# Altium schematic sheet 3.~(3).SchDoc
size 420 x 297 mm
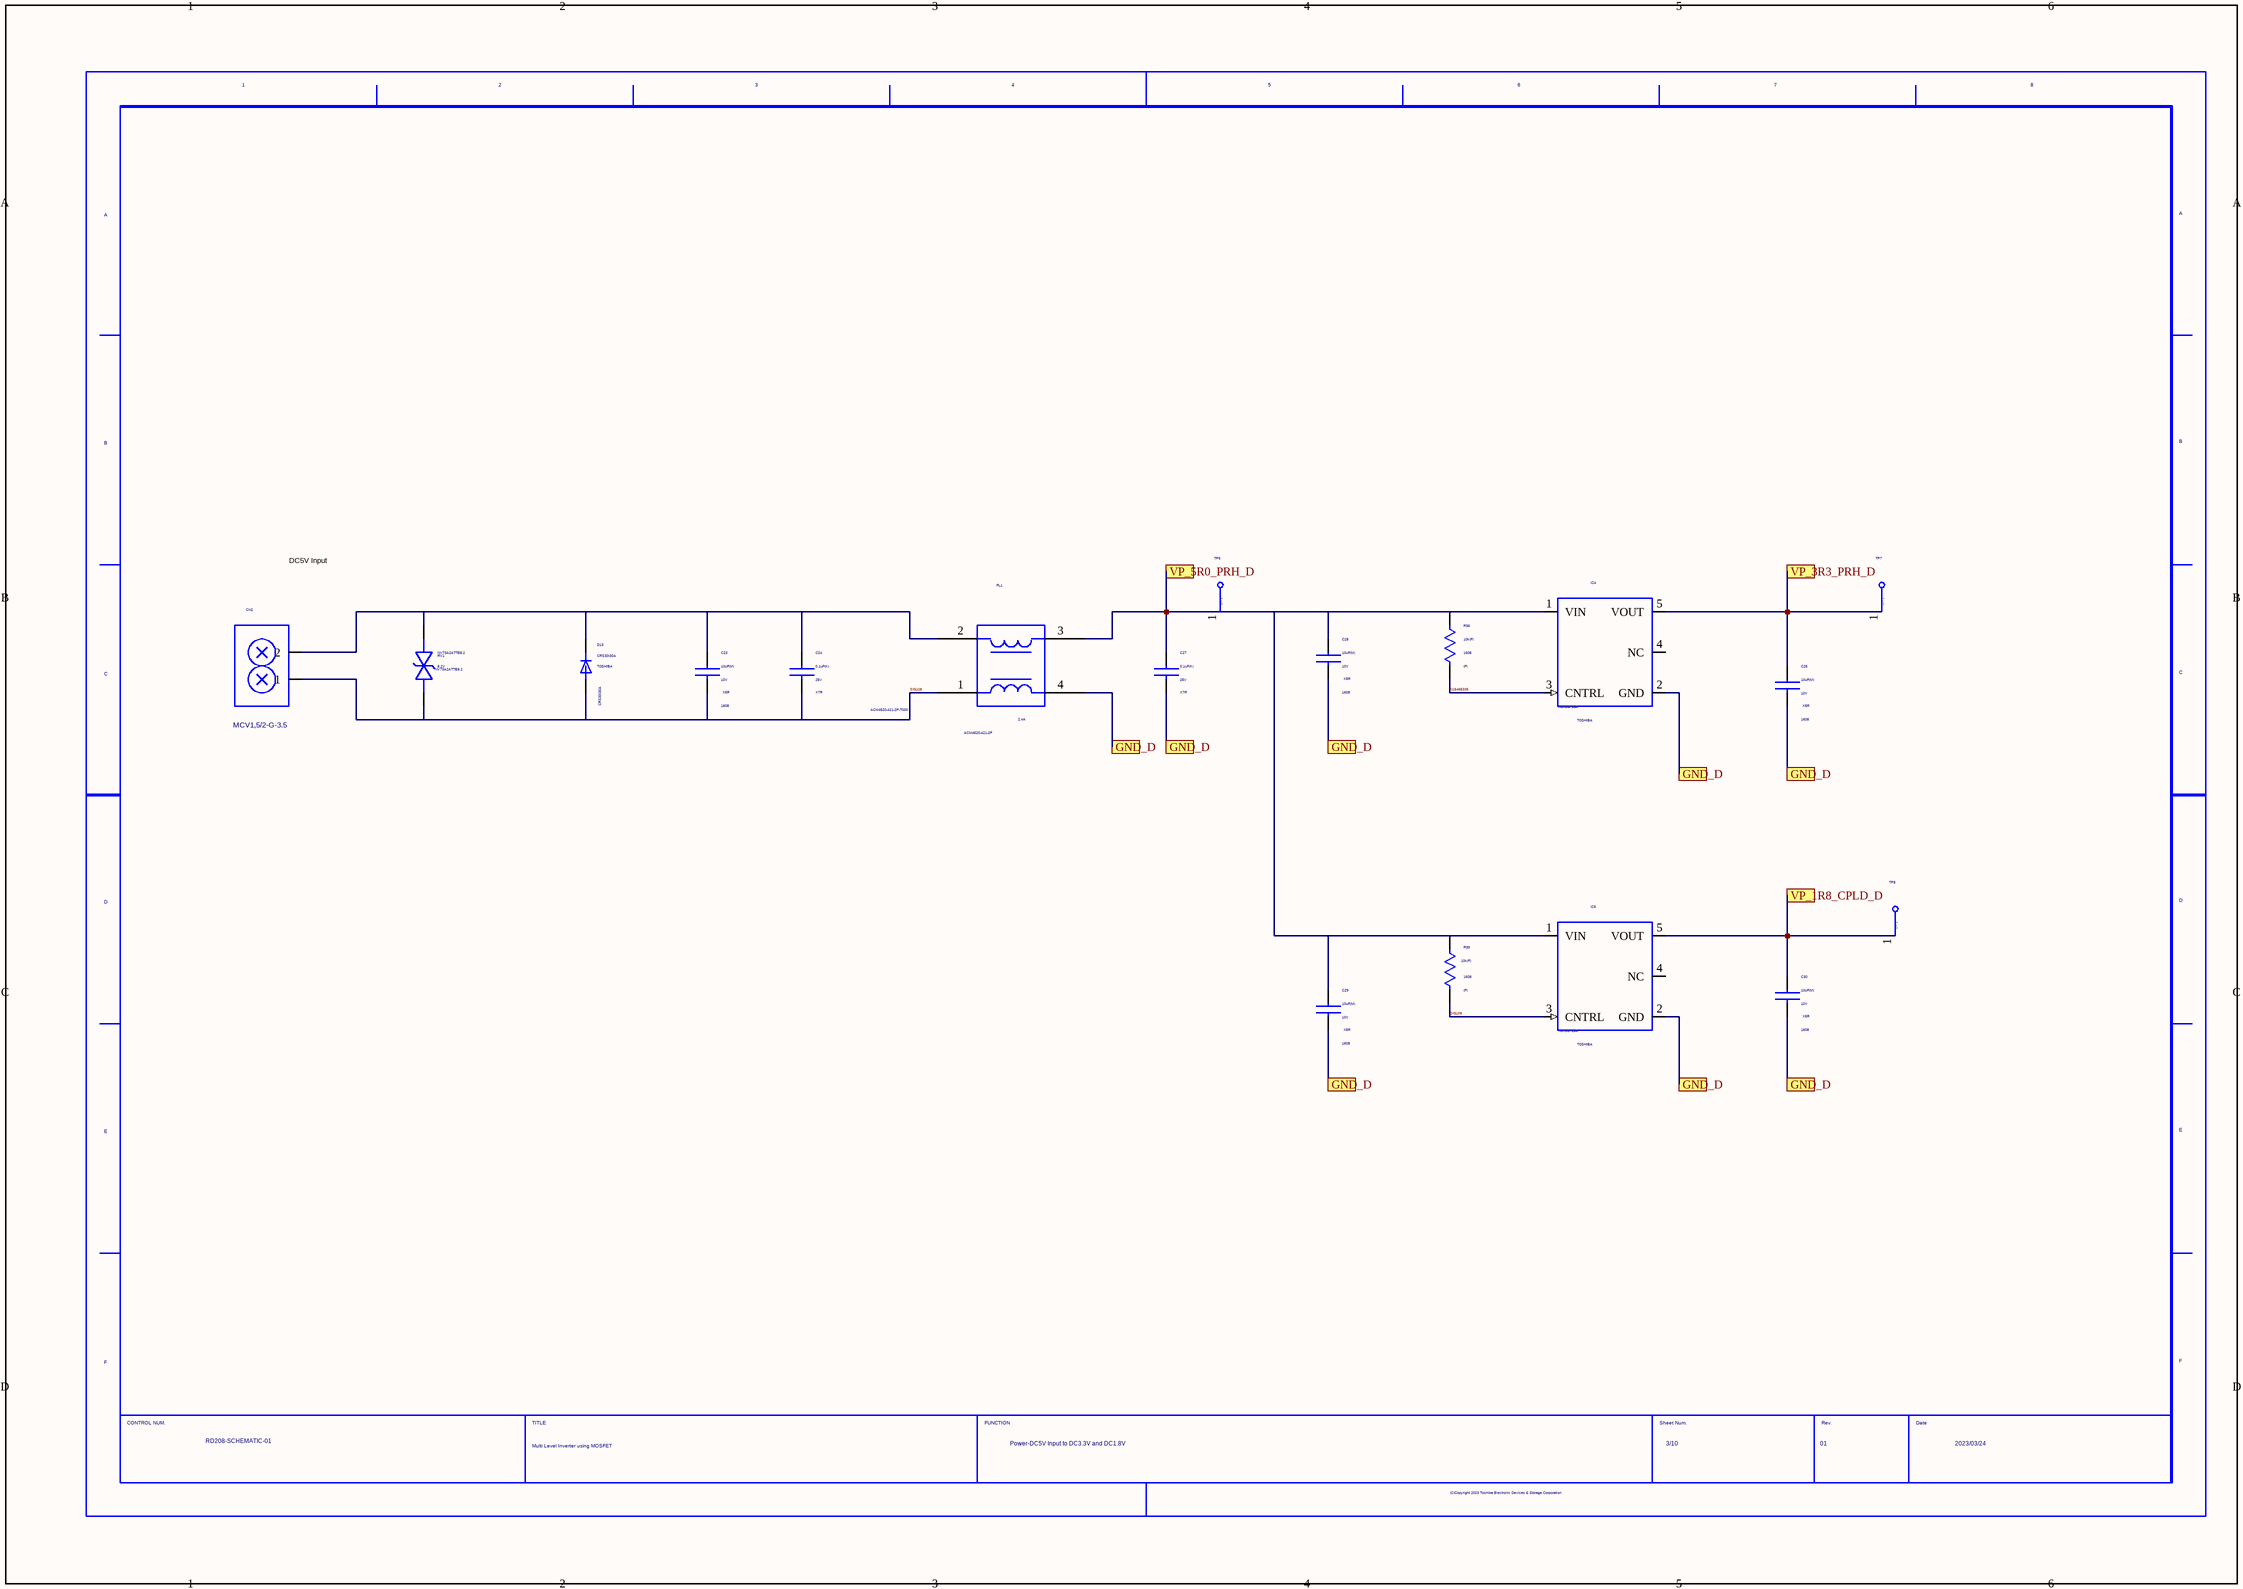
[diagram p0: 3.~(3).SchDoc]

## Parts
C23  VAL2: 10V  SIZECODESMD: 1608  VALUE4: X5R  VAL1: 10uF(M)  (hidden comment: GRM188R61A106ME69D)
C24  VAL2: 25V  VALUE4: X7R  VAL1: 0.1uF(K)  (hidden comment: GRM155R71E104KE14D)
C25  VAL2: 10V  SIZECODESMD: 1608  VALUE4: X5R  VAL1: 10uF(M)  (hidden comment: GRM188R61A106ME69D)
C27  VAL2: 25V  VALUE4: X7R  VAL1: 0.1uF(K)  (hidden comment: GRM155R71E104KE14D)
C28  VAL2: 10V  SIZECODESMD: 1608  VALUE4: X5R  VAL1: 10uF(M)  (hidden comment: GRM188R61A106ME69D)
C29  VAL2: 10V  SIZECODESMD: 1608  VALUE4: X5R  VAL1: 10uF(M)  (hidden comment: GRM188R61A106ME69D)
C30  VAL2: 10V  SIZECODESMD: 1608  VALUE4: X5R  VAL1: 10uF(M)  (hidden comment: GRM188R61A106ME69D)
CN2  SCH_NAME: MCV1,5/2-G-3.5  (hidden comment: 1843606)
D13  USERCOMPTEXT3: TOSHIBA  (hidden comment: CRS30I30A)
FL1  VAL2: 2.4A  VAL1: ACM4520-421-2P-T000  SCH_NAME: ACM4520-421-2P  (hidden comment: ACM4520_421_2P_T000)
IC4  USERCOMPTEXT3: TOSHIBA  (hidden comment: TCR3UF33A)
IC5  USERCOMPTEXT3: TOSHIBA  VAL3: TCR3UF18A  (hidden comment: TCR3UF33A)
R36  SIZECODESMD: 1608  VALUE4: (F)  VAL1: 10k(F)  (hidden comment: ERJ3EKF1002V)
R39  SIZECODESMD: 1608  VALUE4: (F)  VAL1: 10k(F)  (hidden comment: ERJ3EKF1002V)
RV1  VAL2: 8.2V  VAL1: NV73A2ATTE8.2  (hidden comment: NV73A2ATTE8_2)
TP6  TP  (value not drawn)
TP7  TP  (value not drawn)
TP8  TP  (value not drawn)
U?  DATE: 2023/03/24  TITLE: Multi Level Inverter using MOSFET  DRAWINGNUMBER: RD208-SCHEMATIC-01  REVISION: 01  SHEETNUMBER: 3/10  FUNCTION: Power-DC5V Input to DC3.3V and DC1.8V  (hidden comment: WAKU_DEF100)

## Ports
GND_D, VP_1R8_CPLD_D, VP_3R3_PRH_D, VP_5R0_PRH_D

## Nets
5V_IN: C23.1 C24.1 CN2.2 D13.K(CATHODE) FL1.2(CB) RV1.2(C)
GND_D: C25.2 C27.2 C28.2 C29.2 C30.2 FL1.4(CG4) IC4.2(GND) IC5.2(GND) ; port GND_D
N16465335: IC4.3(CNTRL) R36.2
SIG108: C23.2 C24.2 CN2.1 D13.A(ANODE) FL1.1(B) RV1.1(A)
SIG109: IC5.3(CNTRL) R39.2
VP_1R8_CPLD_D: C30.1 IC5.5(VOUT) TP8.1 ; port VP_1R8_CPLD_D
VP_3R3_PRH_D: C25.1 IC4.5(VOUT) TP7.1 ; port VP_3R3_PRH_D
VP_5R0_PRH_D: C27.1 C28.1 C29.1 FL1.3(PSG) IC4.1(VIN) IC5.1(VIN) R36.1 R39.1 TP6.1 ; port VP_5R0_PRH_D

Not connected (* = marked no-connect by the designer): IC4 4(NC); IC5 4(NC)

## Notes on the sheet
- DC5V Input

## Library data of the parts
C23 = GRM188R61A106ME69D: MANUFACTURER: MURATA; ITEM: CAP Ceramic; TIME: 08:44:46; UPDATEUSER: t5459927; SAVECOUNT: 1; OriginalSymbolOrigin: (0,0); INSTANCENAME: INS16466301
C24 = GRM155R71E104KE14D: MANUFACTURER: MURATA; ITEM: CAP Ceramic; SIZECODESMD: 1005; TIME: 08:44:45; UPDATEUSER: t5459927; SAVECOUNT: 1; OriginalSymbolOrigin: (0,0); INSTANCENAME: INS16466561
C25 = GRM188R61A106ME69D: MANUFACTURER: MURATA; ITEM: CAP Ceramic; TIME: 08:44:46; UPDATEUSER: t5459927; SAVECOUNT: 1; OriginalSymbolOrigin: (0,0); INSTANCENAME: INS16465857
C27 = GRM155R71E104KE14D: MANUFACTURER: MURATA; ITEM: CAP Ceramic; SIZECODESMD: 1005; TIME: 08:44:45; UPDATEUSER: t5459927; SAVECOUNT: 1; OriginalSymbolOrigin: (0,0); INSTANCENAME: INS16466055
C28 = GRM188R61A106ME69D: MANUFACTURER: MURATA; ITEM: CAP Ceramic; TIME: 08:44:46; UPDATEUSER: t5459927; SAVECOUNT: 1; OriginalSymbolOrigin: (0,0); INSTANCENAME: INS16466267
C29 = GRM188R61A106ME69D: MANUFACTURER: MURATA; ITEM: CAP Ceramic; TIME: 08:44:46; UPDATEUSER: t5459927; SAVECOUNT: 1; OriginalSymbolOrigin: (0,0); INSTANCENAME: INS16465891
C30 = GRM188R61A106ME69D: MANUFACTURER: MURATA; ITEM: CAP Ceramic; TIME: 08:44:46; UPDATEUSER: t5459927; SAVECOUNT: 1; OriginalSymbolOrigin: (0,0); INSTANCENAME: INS16466167
CN2 = 1843606: MANUFACTURER: PHOENIX CONTACT; ITEM: Connector 2Pin Terminal Block; TIME: 08:44:48; UPDATEUSER: t5459927; SAVECOUNT: 1; SAVEAREA0: -7641,-15544,14757,852; OriginalSymbolOrigin: (0,0); INSTANCENAME: INS16809162
D13 = CRS30I30A: ITEM: DIODE; TIME: 08:44:48; UPDATEUSER: t5459927; SAVECOUNT: 1; OriginalSymbolOrigin: (0,0); INSTANCENAME: INS17152863
FL1 = ACM4520_421_2P_T000: MANUFACTURER: TDK; ITEM: Filter; TIME: 08:44:48; UPDATEUSER: t5459927; SAVECOUNT: 1; SAVEAREA0: -11402,-15649,23384,1144; OriginalSymbolOrigin: (0,0); INSTANCENAME: INS16465959
IC4 IC5 = TCR3UF33A: ITEM: IC LDO; VAL2: LDO; TIME: 08:44:48; UPDATEUSER: PS4_common_PC; UPDATETIME: 15:57:17; SAVECOUNT: 3; SAVEAREA0: -27364,-26218,44601,6573; OriginalSymbolOrigin: (0,0)
R36 = ERJ3EKF1002V: MANUFACTURER: Panasonic; ITEM: Register; VAL2: 100mW; TIME: 08:44:46; UPDATEUSER: t5459927; SAVECOUNT: 1; OriginalSymbolOrigin: (0,0); INSTANCENAME: INS16466335
R39 = ERJ3EKF1002V: MANUFACTURER: Panasonic; ITEM: Register; VAL2: 100mW; TIME: 08:44:46; UPDATEUSER: t5459927; SAVECOUNT: 1; OriginalSymbolOrigin: (0,0); INSTANCENAME: INS16465707
RV1 = NV73A2ATTE8_2: MANUFACTURER: KOA; ITEM: Varistor 8.2V; SIZECODESMD: 2012; TIME: 08:44:47; UPDATEUSER: t5459927; SAVECOUNT: 1; OriginalSymbolOrigin: (0,0); INSTANCENAME: INS16465533
TP6-TP8 = TP: TIME: 16:12:21; UPDATEUSER: fukuda-y; UPDATETIME: 16:18:11; SAVECOUNT: 2; SAVEAREA0: -242,-92,12810,7836; OriginalSymbolOrigin: (0,7620); VAL3: TH Hole dia. 1.0; COMP: TP-TH1.0-L1.6
U? = WAKU_DEF100: PLOTTIME: HH:MM; SAVEAREA0: 185750,-43960,448537,75779; TIME: 14:30:25; UPDATEUSER: PS4_common_PC; UPDATETIME: 08:24:18; SAVECOUNT: 8; OriginalSymbolOrigin: (10160,284480)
